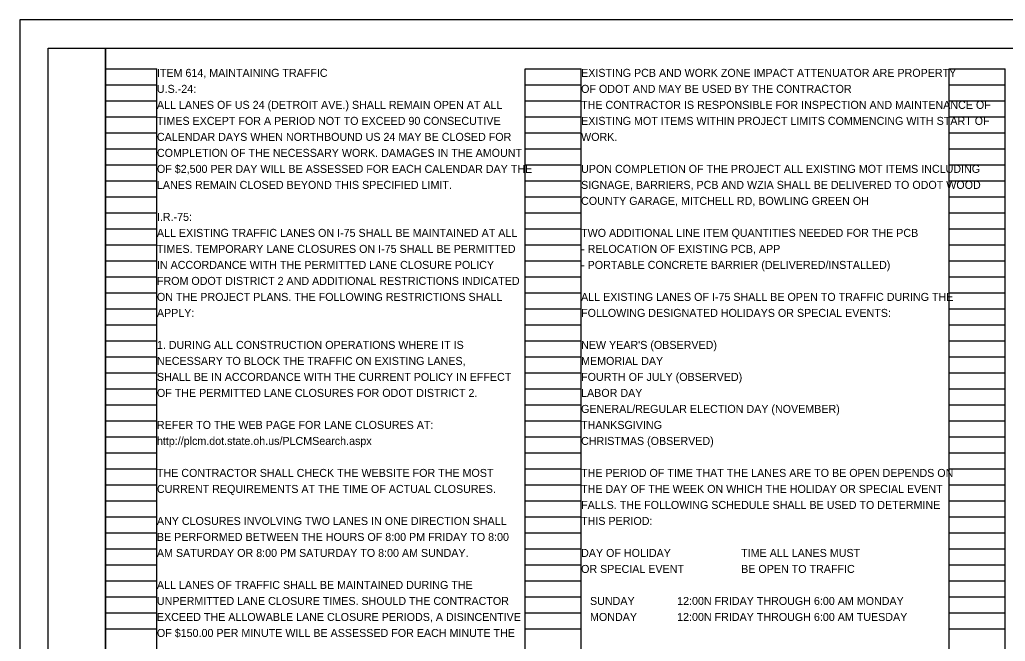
# Model space of a CAD drawing. Extents: x -53 to 237, y -2 to 24.
# Drawn here: x -53.49 to -36.25, y 12.79 to 23.66 of the extents above; entities that cross this region are included whole.
import ezdxf

# ---------------------------------------------------------------- set-up
doc = ezdxf.new("R2010")
doc.units = 0
for name, color, linetype in [('SH_Text', 7, 'Continuous'), ('SN_P_Signs', 7, 'Continuous'), ('SN_X_Text', 7, 'Continuous')]:
    doc.layers.add(name, color=color, linetype=linetype)

msp = doc.modelspace()

# ---------------------------------------------------------------- linework, layer by layer
at = {"layer": 'SH_Text'}
for p, q in [((-51.994, 2.643), (-51.994, 22.803)), ((-51.994, 22.803), (-51.094, 22.803)), ((-51.094, 2.643), (-51.094, 22.803)), ((-44.654, 2.643), (-44.654, 22.803)), ((-44.654, 22.803), (-43.674, 22.803)), ((-43.674, 2.643), (-43.674, 22.803)), ((-37.234, 2.643), (-37.234, 22.803)), ((-37.234, 22.803), (-36.254, 22.803)), ((-36.254, 2.643), (-36.254, 22.803)), ((-51.994, 22.523), (-51.094, 22.523)), ((-44.654, 22.523), (-43.674, 22.523)), ((-37.234, 22.523), (-36.254, 22.523)), ((-51.994, 22.243), (-51.094, 22.243)), ((-44.654, 22.243), (-43.674, 22.243)), ((-37.234, 22.243), (-36.254, 22.243)), ((-51.994, 21.963), (-51.094, 21.963)), ((-44.654, 21.963), (-43.674, 21.963)), ((-37.234, 21.963), (-36.254, 21.963)), ((-51.994, 21.683), (-51.094, 21.683)), ((-44.654, 21.683), (-43.674, 21.683)), ((-37.234, 21.683), (-36.254, 21.683)), ((-51.994, 21.403), (-51.094, 21.403)), ((-44.654, 21.403), (-43.674, 21.403)), ((-37.234, 21.403), (-36.254, 21.403)), ((-51.994, 21.123), (-51.094, 21.123)), ((-44.654, 21.123), (-43.674, 21.123)), ((-37.234, 21.123), (-36.254, 21.123)), ((-51.994, 20.843), (-51.094, 20.843)), ((-44.654, 20.843), (-43.674, 20.843)), ((-37.234, 20.843), (-36.254, 20.843)), ((-51.994, 20.563), (-51.094, 20.563)), ((-44.654, 20.563), (-43.674, 20.563)), ((-37.234, 20.563), (-36.254, 20.563)), ((-51.994, 20.283), (-51.094, 20.283)), ((-44.654, 20.283), (-43.674, 20.283)), ((-37.234, 20.283), (-36.254, 20.283)), ((-51.994, 20.003), (-51.094, 20.003)), ((-44.654, 20.003), (-43.674, 20.003)), ((-37.234, 20.003), (-36.254, 20.003)), ((-51.994, 19.723), (-51.094, 19.723)), ((-44.654, 19.723), (-43.674, 19.723)), ((-37.234, 19.723), (-36.254, 19.723)), ((-51.994, 19.443), (-51.094, 19.443)), ((-44.654, 19.443), (-43.674, 19.443)), ((-37.234, 19.443), (-36.254, 19.443)), ((-51.994, 19.163), (-51.094, 19.163)), ((-44.654, 19.163), (-43.674, 19.163)), ((-37.234, 19.163), (-36.254, 19.163)), ((-51.994, 18.883), (-51.094, 18.883)), ((-44.654, 18.883), (-43.674, 18.883)), ((-37.234, 18.883), (-36.254, 18.883)), ((-51.994, 18.603), (-51.094, 18.603)), ((-44.654, 18.603), (-43.674, 18.603)), ((-37.234, 18.603), (-36.254, 18.603)), ((-51.994, 18.323), (-51.094, 18.323)), ((-44.654, 18.323), (-43.674, 18.323)), ((-37.234, 18.323), (-36.254, 18.323)), ((-51.994, 18.043), (-51.094, 18.043)), ((-44.654, 18.043), (-43.674, 18.043)), ((-37.234, 18.043), (-36.254, 18.043)), ((-51.994, 17.763), (-51.094, 17.763)), ((-44.654, 17.763), (-43.674, 17.763)), ((-37.234, 17.763), (-36.254, 17.763)), ((-51.994, 17.483), (-51.094, 17.483)), ((-44.654, 17.483), (-43.674, 17.483)), ((-37.234, 17.483), (-36.254, 17.483)), ((-51.994, 17.203), (-51.094, 17.203)), ((-44.654, 17.203), (-43.674, 17.203)), ((-37.234, 17.203), (-36.254, 17.203)), ((-51.994, 16.923), (-51.094, 16.923)), ((-44.654, 16.923), (-43.674, 16.923)), ((-37.234, 16.923), (-36.254, 16.923)), ((-51.994, 16.643), (-51.094, 16.643)), ((-44.654, 16.643), (-43.674, 16.643)), ((-37.234, 16.643), (-36.254, 16.643)), ((-51.994, 16.363), (-51.094, 16.363)), ((-44.654, 16.363), (-43.674, 16.363)), ((-37.234, 16.363), (-36.254, 16.363)), ((-51.994, 16.083), (-51.094, 16.083)), ((-44.654, 16.083), (-43.674, 16.083)), ((-37.234, 16.083), (-36.254, 16.083)), ((-51.994, 15.803), (-51.094, 15.803)), ((-44.654, 15.803), (-43.674, 15.803)), ((-37.234, 15.803), (-36.254, 15.803)), ((-51.994, 15.523), (-51.094, 15.523)), ((-44.654, 15.523), (-43.674, 15.523)), ((-37.234, 15.523), (-36.254, 15.523)), ((-51.994, 15.243), (-51.094, 15.243)), ((-44.654, 15.243), (-43.674, 15.243)), ((-37.234, 15.243), (-36.254, 15.243)), ((-51.994, 14.963), (-51.094, 14.963)), ((-44.654, 14.963), (-43.674, 14.963)), ((-37.234, 14.963), (-36.254, 14.963)), ((-51.994, 14.683), (-51.094, 14.683)), ((-44.654, 14.683), (-43.674, 14.683)), ((-37.234, 14.683), (-36.254, 14.683)), ((-51.994, 14.403), (-51.094, 14.403)), ((-44.654, 14.403), (-43.674, 14.403)), ((-37.234, 14.403), (-36.254, 14.403)), ((-51.994, 14.123), (-51.094, 14.123)), ((-44.654, 14.123), (-43.674, 14.123)), ((-37.234, 14.123), (-36.254, 14.123)), ((-51.994, 13.843), (-51.094, 13.843)), ((-44.654, 13.843), (-43.674, 13.843)), ((-37.234, 13.843), (-36.254, 13.843)), ((-51.994, 13.563), (-51.094, 13.563)), ((-44.654, 13.563), (-43.674, 13.563)), ((-37.234, 13.563), (-36.254, 13.563)), ((-51.994, 13.283), (-51.094, 13.283)), ((-44.654, 13.283), (-43.674, 13.283)), ((-37.234, 13.283), (-36.254, 13.283)), ((-51.994, 13.003), (-51.094, 13.003)), ((-44.654, 13.003), (-43.674, 13.003)), ((-37.234, 13.003), (-36.254, 13.003))]:
    msp.add_line(p, q, dxfattribs=at)
at = {"layer": 'SN_X_Text'}
for points in [[(-53.494, 1.663), (-19.494, 1.663), (-19.494, 23.663), (-53.494, 23.663)], [(-52.994, 23.163), (-51.994, 23.163), (-51.994, 2.163), (-52.994, 2.163)], [(-51.994, 23.163), (-19.994, 23.163), (-19.994, 2.163), (-51.994, 2.163)]]:
    msp.add_lwpolyline(points, close=True, dxfattribs=at)

# ---------------------------------------------------------------- texts
at = {"layer": 'SN_P_Signs'}
for s, p in [('ITEM 614, MAINTAINING TRAFFIC', (-51.094, 22.663)), ('EXISTING PCB AND WORK ZONE IMPACT ATTENUATOR ARE PROPERTY', (-43.674, 22.663)), ('U.S.-24:', (-51.094, 22.383)), ('OF ODOT AND MAY BE USED BY THE CONTRACTOR', (-43.674, 22.383)), ('ALL LANES OF US 24 (DETROIT AVE.) SHALL REMAIN OPEN AT ALL ', (-51.094, 22.103)), ('THE CONTRACTOR IS RESPONSIBLE FOR INSPECTION AND MAINTENANCE OF', (-43.674, 22.103)), ('TIMES EXCEPT FOR A PERIOD NOT TO EXCEED 90 CONSECUTIVE ', (-51.094, 21.823)), ('EXISTING MOT ITEMS WITHIN PROJECT LIMITS COMMENCING WITH START OF', (-43.674, 21.823)), ('CALENDAR DAYS WHEN NORTHBOUND US 24 MAY BE CLOSED FOR ', (-51.094, 21.543)), ('WORK.', (-43.674, 21.543)), ('COMPLETION OF THE NECESSARY WORK. DAMAGES IN THE AMOUNT ', (-51.094, 21.263)), ('OF $2,500 PER DAY WILL BE ASSESSED FOR EACH CALENDAR DAY THE ', (-51.094, 20.983)), ('UPON COMPLETION OF THE PROJECT ALL EXISTING MOT ITEMS INCLUDING', (-43.674, 20.983)), ('LANES REMAIN CLOSED BEYOND THIS SPECIFIED LIMIT.', (-51.094, 20.703)), ('SIGNAGE, BARRIERS, PCB AND WZIA SHALL BE DELIVERED TO ODOT WOOD', (-43.674, 20.703)), ('COUNTY GARAGE, MITCHELL RD, BOWLING GREEN OH', (-43.674, 20.423)), ('I.R.-75:', (-51.094, 20.143)), ('ALL EXISTING TRAFFIC LANES ON I-75 SHALL BE MAINTAINED AT ALL', (-51.094, 19.863)), ('TWO ADDITIONAL LINE ITEM QUANTITIES NEEDED FOR THE PCB', (-43.674, 19.863)), ('TIMES. TEMPORARY LANE CLOSURES ON I-75 SHALL BE PERMITTED', (-51.094, 19.583)), ('- RELOCATION OF EXISTING PCB, APP', (-43.674, 19.583)), ('IN ACCORDANCE WITH THE PERMITTED LANE CLOSURE POLICY', (-51.094, 19.303)), ('- PORTABLE CONCRETE BARRIER (DELIVERED/INSTALLED)', (-43.674, 19.303)), ('FROM ODOT DISTRICT 2 AND ADDITIONAL RESTRICTIONS INDICATED', (-51.094, 19.023)), ('ON THE PROJECT PLANS. THE FOLLOWING RESTRICTIONS SHALL', (-51.094, 18.743)), ('ALL EXISTING LANES OF I-75 SHALL BE OPEN TO TRAFFIC DURING THE ', (-43.674, 18.743)), ('APPLY:', (-51.094, 18.463)), ('FOLLOWING DESIGNATED HOLIDAYS OR SPECIAL EVENTS:', (-43.674, 18.463)), ('1. DURING ALL CONSTRUCTION OPERATIONS WHERE IT IS', (-51.094, 17.903)), ("NEW YEAR'S (OBSERVED)", (-43.674, 17.903)), ('NECESSARY TO BLOCK THE TRAFFIC ON EXISTING LANES,', (-51.094, 17.623)), ('MEMORIAL DAY', (-43.674, 17.623)), ('SHALL BE IN ACCORDANCE WITH THE CURRENT POLICY IN EFFECT', (-51.094, 17.343)), ('FOURTH OF JULY (OBSERVED)', (-43.674, 17.343)), ('OF THE PERMITTED LANE CLOSURES FOR ODOT DISTRICT 2.', (-51.094, 17.063)), ('LABOR DAY', (-43.674, 17.063)), ('GENERAL/REGULAR ELECTION DAY (NOVEMBER)', (-43.674, 16.783)), ('REFER TO THE WEB PAGE FOR LANE CLOSURES AT:', (-51.094, 16.503)), ('THANKSGIVING', (-43.674, 16.503)), ('http://plcm.dot.state.oh.us/PLCMSearch.aspx', (-51.094, 16.223)), ('CHRISTMAS (OBSERVED)', (-43.674, 16.223)), ('THE CONTRACTOR SHALL CHECK THE WEBSITE FOR THE MOST', (-51.094, 15.663)), ('THE PERIOD OF TIME THAT THE LANES ARE TO BE OPEN DEPENDS ON ', (-43.674, 15.663)), ('CURRENT REQUIREMENTS AT THE TIME OF ACTUAL CLOSURES.', (-51.094, 15.383)), ('THE DAY OF THE WEEK ON WHICH THE HOLIDAY OR SPECIAL EVENT ', (-43.674, 15.383)), ('FALLS. THE FOLLOWING SCHEDULE SHALL BE USED TO DETERMINE ', (-43.674, 15.103)), ('ANY CLOSURES INVOLVING TWO LANES IN ONE DIRECTION SHALL', (-51.094, 14.823)), ('THIS PERIOD:', (-43.674, 14.823)), ('BE PERFORMED BETWEEN THE HOURS OF 8:00 PM FRIDAY TO 8:00', (-51.094, 14.543)), ('AM SATURDAY OR 8:00 PM SATURDAY TO 8:00 AM SUNDAY.', (-51.094, 14.263)), ('DAY OF HOLIDAY', (-43.674, 14.263)), ('TIME ALL LANES MUST', (-40.874, 14.263)), ('OR SPECIAL EVENT', (-43.674, 13.983)), ('BE OPEN TO TRAFFIC', (-40.874, 13.983)), ('ALL LANES OF TRAFFIC SHALL BE MAINTAINED DURING THE', (-51.094, 13.703)), ('UNPERMITTED LANE CLOSURE TIMES. SHOULD THE CONTRACTOR', (-51.094, 13.423)), ('   SUNDAY     ', (-43.674, 13.423)), ('12:00N FRIDAY THROUGH 6:00 AM MONDAY', (-41.994, 13.423)), ('EXCEED THE ALLOWABLE LANE CLOSURE PERIODS, A DISINCENTIVE', (-51.094, 13.143)), ('   MONDAY     ', (-43.674, 13.143)), ('12:00N FRIDAY THROUGH 6:00 AM TUESDAY', (-41.994, 13.143)), ('OF $150.00 PER MINUTE WILL BE ASSESSED FOR EACH MINUTE THE', (-51.094, 12.863))]:
    msp.add_text(s, height=0.14, dxfattribs=at).set_placement(p)

doc.saveas('drawing.dxf')
